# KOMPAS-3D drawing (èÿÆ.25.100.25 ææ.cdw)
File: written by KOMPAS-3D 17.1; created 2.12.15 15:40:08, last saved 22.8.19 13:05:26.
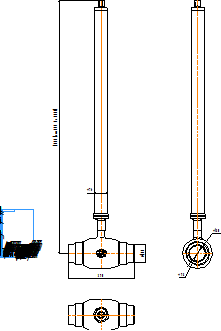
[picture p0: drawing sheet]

Sheet 1: A4, portrait

Title block, sheet 1: name: КШТ.25.100.25 С/С; sheets: 1; organisation: ООО "АДЛ Групп"; sheet format: A4; stored path: C:\Users\kka\KOMPAS_Work\Модели кранов для исследований\DN50\С удлинением\КШГ.32.050.40 СС ГЧ _ Шаровой кран БИВАЛ Ду50 Ру4 МПа редуцированный под приварку, с удлинением штока H=1100.cdw

Views: Вид 1, Проекционный вид 3
Referenced files in C:\Users\kka\KOMPAS_Work\Модели кранов для исследований\DN80\С удлинением\: КШТ.22.080.25 СС.a3d, КШГ.35.065.25 СС.a3d!КШГ.45.065.10 СС!Деталь (локальная).m3d
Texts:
  Klimkovich
  ADL
  (от 377 до 5000)
  Рама для чертежей
  Лит-Масса-Масштаб
  Материал-Предприятие
  Масштаб
  Изм.
  Лист
  № докум.
  Подп.
  Дата
  Лит.
  Разраб.
  Пров.
  Т.контр.
  Листов
  Внимание! Данный продукт является объектом авторского права ООО «Торговый Дом АДЛ».
  Запрещается изменение, копирование, распространение
  (в том числе путем копирования на другие сайты и ресурсы в Интернете)
  или любое иное использование информации и объектов без предварительного
  согласия правообладателя (ООО «Торговый Дом АДЛ»).
  Н.контр.
  Утв.
  ООО "Торговый дом АДЛ"
  Изменение
  Номер документа
  Подпись
  Обозначение документа
  Наименование изделия
  Масса изделия по ГОСТ 2.109-73
  Порядковый номер листа
  Общее количество листов в документе
  Характер работы, выполненной лицом, подписавшим документ
  Наименование или индекс предприятия, выпускающего документ
  Инв. № подл.
  Подп. и дата
  Взам. инв. №
  Инв. № дубл.
  Инвентарный номер подлинника по ГОСТ 2.501-68
  Подпись принявшего подлинник в отдел технической документации
  Инвентарный номер подлинника, взамен которого выпущен данный подлинник
  Инвентарный номер дубликата по ГОСТ 2.502-68
  Подпись принявшего дубликат в отдел технической документации
  Справ. №
  Перв. примен.
  Обозначение документа, взамен или на основании которого выпущен данный документ
  Обозначение документа, в котором впервые записан данный документ
  Подпись лица, копировавшего чертеж
  Обозначение формата листа
  !Рама для чертежа
Dimensions and other numbers on the sheet: 1500; 76; 390; 108; 1:1; 1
